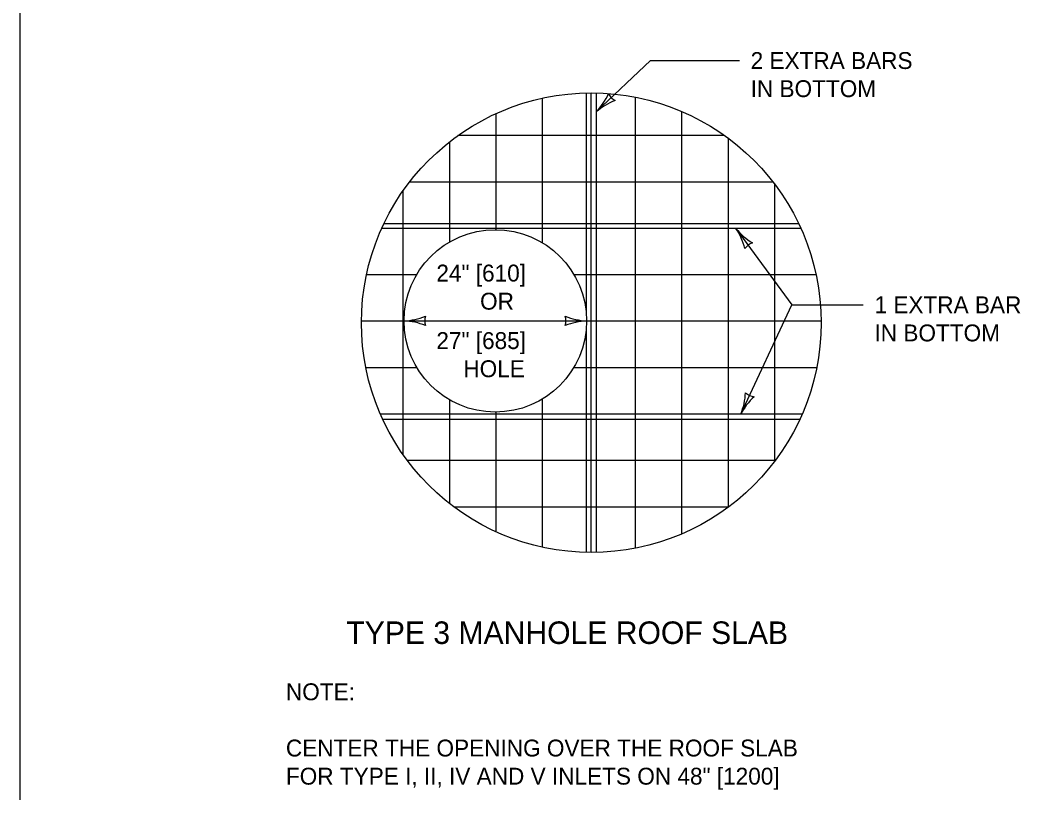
# Model space of a CAD drawing. Extents: x 49991.4 to 50028.3, y 49987.6 to 50011.4.
# Drawn here: x 49999.384 to 50002.994, y 49990.664 to 49993.409 of the extents above; entities that cross this region are included whole.
import ezdxf

# ---------------------------------------------------------------- set-up
doc = ezdxf.new("R2010")
doc.units = 0
for name, color, linetype in [('Level 1', 7, 'Continuous'), ('Level 2', 7, 'Continuous'), ('Level 3', 7, 'Continuous')]:
    doc.layers.add(name, color=color, linetype=linetype)

msp = doc.modelspace()

# ---------------------------------------------------------------- linework, layer by layer
at = {"layer": 'Level 1'}
for p, q in [((50001.3943, 49993.1505), (50001.3943, 49992.3653)), ((50001.4119, 49991.5175), (50001.4119, 49993.1506)), ((50001.4295, 49993.1506), (50001.4295, 49991.5177)), ((50001.2389, 49992.618), (50001.2389, 49993.1321)), ((50001.5689, 49991.5327), (50001.5689, 49993.1354)), ((50001.7339, 49991.5837), (50001.7339, 49993.0845)), ((50001.0739, 49992.6648), (50001.0739, 49993.0775)), ((50000.9089, 49992.6214), (50000.9089, 49992.9774)), ((50001.8855, 49992.9992), (50000.9382, 49992.9992)), ((50001.8989, 49991.6786), (50001.8989, 49992.9895)), ((50002.0573, 49992.8342), (50000.7664, 49992.8342)), ((50002.0639, 49991.8425), (50002.0639, 49992.8256)), ((50000.7439, 49991.8643), (50000.7439, 49992.8038)), ((50000.6752, 49992.6863), (50002.1485, 49992.6863)), ((50002.1564, 49992.6692), (50000.6672, 49992.6692)), ((50000.791, 49992.5042), (50000.6133, 49992.5042)), ((50002.2105, 49992.5042), (50001.351, 49992.5042)), ((50000.7468, 49992.3392), (50000.5953, 49992.3392)), ((50002.2284, 49992.3392), (50001.3952, 49992.3392)), ((50001.3943, 49992.316), (50001.3943, 49991.5177)), ((50000.7928, 49992.1742), (50000.6112, 49992.1742)), ((50002.2126, 49992.1742), (50001.3492, 49992.1742)), ((50000.9089, 49991.6908), (50000.9089, 49992.0599)), ((50001.2389, 49991.536), (50001.2389, 49992.0633)), ((50002.1611, 49992.0092), (50000.6627, 49992.0092)), ((50001.0739, 49991.5907), (50001.0739, 49992.0164)), ((50000.6707, 49991.9913), (50002.153, 49991.9913)), ((50002.0653, 49991.8442), (50000.7585, 49991.8442)), ((50001.8997, 49991.6792), (50000.924, 49991.6792))]:
    msp.add_line(p, q, dxfattribs=at)
msp.add_lwpolyline([(49999.3835, 49998.9992), (50016.7501, 49998.9992), (50016.7501, 49987.7988), (49999.3835, 49987.7988)], close=True, dxfattribs=at)
for centre, radius in [((50001.4118, 49992.3341), 0.8166), ((50001.071, 49992.3407), 0.3242)]:
    msp.add_circle(centre, radius, dxfattribs=at)
at = {"layer": 'Level 3'}
for p, q in [((50001.926, 49992.6692), (50002.1242, 49992.3979)), ((50001.943, 49992.0092), (50002.1242, 49992.3979)), ((50002.1242, 49992.3979), (50002.3781, 49992.3979)), ((50000.7468, 49992.3407), (50001.3952, 49992.3407))]:
    msp.add_line(p, q, dxfattribs=at)
msp.add_lwpolyline([(50001.4295, 49993.0836), (50001.6224, 49993.2661), (50001.9381, 49993.2661)], dxfattribs=at)
for centre, radius, start, end in [((50001.2612, 49993.2447), 0.233, 316.2439, 335.4938), ((50001.5755, 49992.916), 0.2223, 110.8726, 131.0561), ((50001.5226, 49993.1717), 0.0548, 205.5554, 241.2778), ((50001.7412, 49992.5456), 0.2223, 13.5979, 33.7814), ((50002.1071, 49992.8158), 0.233, 218.9692, 238.2191), ((50002.0016, 49992.5657), 0.0548, 108.2807, 144.0031), ((50000.7353, 49992.5734), 0.233, 272.8273, 292.0772), ((50000.875, 49992.3407), 0.0548, 162.1388, 197.8612), ((50001.4044, 49992.5629), 0.2223, 247.456, 267.6395), ((50001.267, 49992.3407), 0.0548, 342.1388, 17.8612), ((50000.7377, 49992.1186), 0.2223, 67.456, 87.6395), ((50001.4067, 49992.108), 0.233, 92.8273, 112.0772), ((50001.7272, 49992.0971), 0.233, 337.8311, 357.081), ((50002.1404, 49991.9071), 0.2223, 132.4598, 152.6433), ((50001.9971, 49992.1254), 0.0548, 227.1426, 262.865)]:
    msp.add_arc(centre, radius, start, end, dxfattribs=at)

# ---------------------------------------------------------------- texts
at = {"layer": 'Level 2'}
for s, height, p in [('2 EXTRA BARS', 0.06, (50001.9781, 49993.2361)), ('IN BOTTOM', 0.06, (50001.9781, 49993.1361)), ('24" [610]', 0.06, (50000.8616, 49992.4807)), ('OR', 0.06, (50001.0168, 49992.3807)), ('1 EXTRA BAR', 0.06, (50002.4181, 49992.3679)), ('IN BOTTOM', 0.06, (50002.4181, 49992.2679)), ('27" [685]', 0.06, (50000.8616, 49992.2407)), ('HOLE', 0.06, (50000.9574, 49992.1407)), ('TYPE 3 MANHOLE ROOF SLAB', 0.08, (50000.5417, 49991.1925)), ('NOTE:', 0.06, (50000.327, 49990.9925)), ('CENTER THE OPENING OVER THE ROOF SLAB', 0.06, (50000.327, 49990.7925)), ('FOR TYPE I, II, IV AND V INLETS ON 48" [1200]', 0.06, (50000.327, 49990.6925))]:
    msp.add_text(s, height=height, dxfattribs=at).set_placement(p)

doc.saveas('drawing.dxf')
